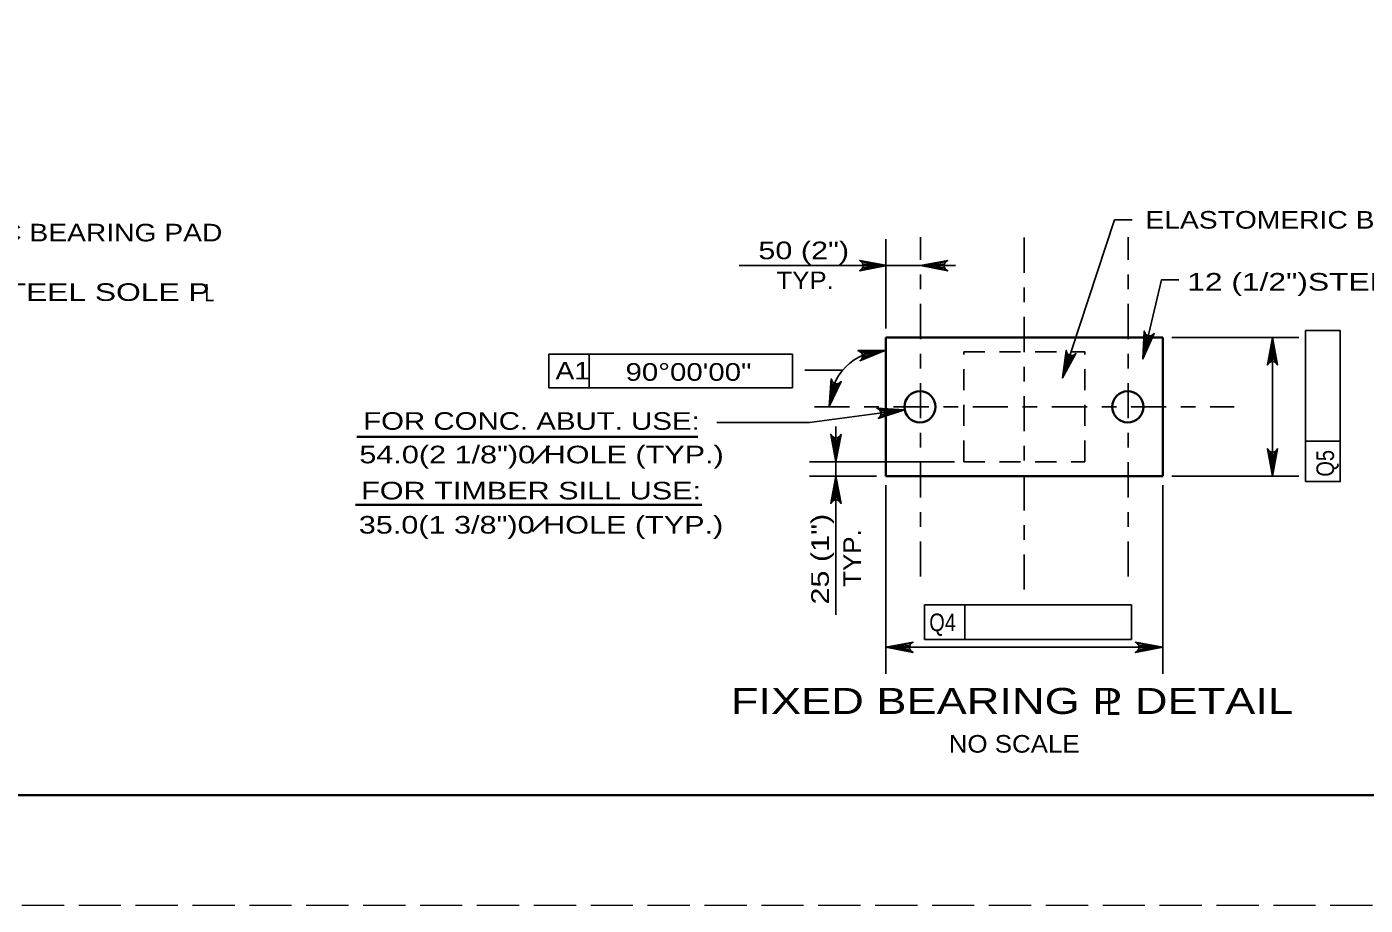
# Model space of a CAD drawing. Extents: x -11 to 79, y -154 to 0.
# Drawn here: x 14 to 23.13, y -154 to -148.01 of the extents above; entities that cross this region are included whole.
import ezdxf
from ezdxf.enums import TextEntityAlignment as Align

# ---------------------------------------------------------------- set-up
doc = ezdxf.new("R2010")
doc.units = 0
doc.header["$LTSCALE"] = 0.048
for name, pattern in [('DOT_DASHED', [7.7, 5, -1.2, 0.3, -1.2]), ('LONG_DASHED', [7.5, 6, -1.5]), ('MEDIUM_DASHED', [4.5, 3, -1.5])]:
    doc.linetypes.add(name, pattern=pattern)
for name, color, linetype, lineweight in [('1', 7, 'Continuous', 25), ('3', 7, 'Continuous', 25), ('4', 7, 'Continuous', 25), ('63', 7, 'LONG_DASHED', 13)]:
    doc.layers.add(name, color=color, linetype=linetype, lineweight=lineweight)

msp = doc.modelspace()

# ---------------------------------------------------------------- hatches: boundary and pattern name
at = {"layer": '4'}
for points in [[(19.74033, -149.61867), (19.74033, -149.65867), (19.86033, -149.63867)], [(20.21658, -149.61867), (20.21658, -149.65867), (20.09658, -149.63867)], [(21.6615, -150.16108), (21.62258, -150.152), (21.61475, -150.27342)], [(22.47825, -150.24958), (22.51825, -150.24958), (22.49825, -150.12958)], [(21.12533, -150.28867), (21.08733, -150.27617), (21.06875, -150.39633)], [(19.86742, -150.61775), (19.87267, -150.65733), (19.989, -150.62167)], [(19.5005, -150.856), (19.5405, -150.856), (19.5205, -150.976)], [(22.47825, -150.95442), (22.51825, -150.95442), (22.49825, -151.07442)], [(19.5005, -151.19442), (19.5405, -151.19442), (19.5205, -151.07442)], [(19.98033, -152.22167), (19.98033, -152.26167), (19.86033, -152.24167)], [(21.63008, -152.22167), (21.63008, -152.26167), (21.75008, -152.24167)]]:
    msp.add_hatch(color=256, dxfattribs=at).paths.add_polyline_path(points)

# ---------------------------------------------------------------- linework, layer by layer
at = {"layer": '1', "lineweight": 35}
msp.add_lwpolyline([(1.75, -153.25), (33.25, -153.25), (33.25, -132.75), (1.75, -132.75)], close=True, dxfattribs=at)
at = {"layer": '3', "lineweight": 35}
for p, q in [((19.86033, -150.12958), (21.75008, -150.12958)), ((19.86033, -151.07442), (19.86033, -150.12958)), ((21.75008, -151.07442), (21.75008, -150.12958)), ((19.86033, -151.07442), (21.75008, -151.07442))]:
    msp.add_line(p, q, dxfattribs=at)
at = {"layer": '3', "linetype": 'MEDIUM_DASHED'}
for p, q in [((21.21858, -150.976), (21.21858, -150.228)), ((20.39183, -150.976), (21.21858, -150.976))]:
    msp.add_line(p, q, dxfattribs=at)
msp.add_lwpolyline([(20.39183, -150.976), (20.39183, -150.228), (21.21858, -150.228)], dxfattribs=at)
at = {"layer": '3', "lineweight": 35}
for centre in [(20.09365, -150.60209), (21.51097, -150.60209)]:
    msp.add_circle(centre, 0.1063, dxfattribs=at)
at = {"layer": '4', "linetype": 'DOT_DASHED'}
for p, q in [((20.80525, -151.8485), (20.80525, -149.3555)), ((20.09658, -151.7595), (20.09658, -149.44442)), ((21.51392, -151.7595), (21.51392, -149.44442)), ((19.37383, -150.602), (22.23658, -150.602))]:
    msp.add_line(p, q, dxfattribs=at)
at = {"layer": '4'}
for p, q in [((19.86033, -150.06708), (19.86033, -149.45867)), ((20.09658, -149.63867), (18.86158, -149.63867)), ((20.21658, -149.63867), (20.33658, -149.63867)), ((21.81092, -150.12958), (22.67825, -150.12958)), ((22.49825, -151.07442), (22.49825, -150.12958)), ((22.72375, -151.11192), (22.72375, -150.08208)), ((22.72375, -150.08208), (22.96, -150.08208)), ((17.56275, -150.24192), (19.22375, -150.24192)), ((17.83842, -150.47258), (17.83842, -150.24192)), ((19.22375, -150.24192), (19.22375, -150.47258)), ((19.56683, -150.35225), (19.30758, -150.35225)), ((19.98917, -150.62167), (19.34083, -150.70808)), ((19.34083, -150.70808), (18.70825, -150.70808)), ((19.5205, -150.856), (19.5205, -150.736)), ((22.96, -150.83633), (22.72375, -150.83633)), ((20.32933, -150.976), (19.3405, -150.976)), ((19.5205, -150.976), (19.5205, -152.01958)), ((19.79783, -151.07442), (19.3405, -151.07442)), ((21.81258, -151.07442), (22.67825, -151.07442)), ((19.86033, -151.13692), (19.86033, -152.42167)), ((21.75008, -151.13692), (21.75008, -152.42167)), ((20.12425, -151.95225), (21.53625, -151.95225)), ((20.12425, -152.1885), (20.12425, -151.95225)), ((20.39983, -152.1885), (20.39983, -151.95225)), ((21.53625, -151.95225), (21.53625, -152.1885)), ((19.86033, -152.24167), (21.75008, -152.24167)), ((21.53625, -152.1885), (20.12425, -152.1885))]:
    msp.add_line(p, q, dxfattribs=at)
at = {"layer": '4', "lineweight": 35}
for p, q in [((16.253, -150.80617), (18.57942, -150.80617)), ((17.4485, -150.98842), (17.56808, -150.86883)), ((16.24442, -151.26992), (18.60583, -151.26992)), ((17.45217, -151.453), (17.5555, -151.34958))]:
    msp.add_line(p, q, dxfattribs=at)
at = {"layer": '4'}
for points in [[(21.06592, -150.40508), (21.42133, -149.327), (21.54133, -149.327)], [(19.86892, -149.63867), (19.6825, -149.67358), (19.69683, -149.66367), (19.70425, -149.65117), (19.70642, -149.63867), (19.70425, -149.62617), (19.69683, -149.61367), (19.6825, -149.60375), (19.86892, -149.63867), (19.69683, -149.61367), (19.70425, -149.62617), (19.86892, -149.63867), (19.70642, -149.63867), (19.70425, -149.65117), (19.86892, -149.63867), (19.69683, -149.66367)], [(20.09658, -149.63867), (20.283, -149.60375), (20.26867, -149.61367), (20.26125, -149.62617), (20.25908, -149.63867), (20.26125, -149.65117), (20.26867, -149.66367), (20.283, -149.67358), (20.09658, -149.63867), (20.26867, -149.66367), (20.26125, -149.65117), (20.09658, -149.63867), (20.25908, -149.63867), (20.26125, -149.62617), (20.09658, -149.63867), (20.26867, -149.61367)], [(21.6145, -150.27467), (21.74025, -149.73658), (21.86025, -149.73658)], [(21.6145, -150.27467), (21.62292, -150.08517), (21.62933, -150.10142), (21.63983, -150.1115), (21.6515, -150.11642), (21.66417, -150.11717), (21.678, -150.11283), (21.69092, -150.10108), (21.6145, -150.27467), (21.678, -150.11283), (21.66417, -150.11717), (21.6145, -150.27467), (21.6515, -150.11642), (21.63983, -150.1115), (21.6145, -150.27467), (21.62933, -150.10142)], [(22.49825, -150.12958), (22.53317, -150.316), (22.52325, -150.30167), (22.51075, -150.29425), (22.49825, -150.29208), (22.48575, -150.29425), (22.47325, -150.30167), (22.46333, -150.316), (22.49825, -150.12958), (22.47325, -150.30167), (22.48575, -150.29425), (22.49825, -150.12958), (22.49825, -150.29208), (22.51075, -150.29425), (22.49825, -150.12958), (22.52325, -150.30167)], [(22.96, -150.08208), (22.96, -151.11192), (22.72375, -151.11192)], [(19.22375, -150.47258), (17.56275, -150.47258), (17.56275, -150.24192)], [(19.86017, -150.21658), (19.68425, -150.2875), (19.69633, -150.27483), (19.70117, -150.26117), (19.70083, -150.2485), (19.69625, -150.23667), (19.6865, -150.22583), (19.6705, -150.21892), (19.86017, -150.21658), (19.6865, -150.22583), (19.69625, -150.23667), (19.86017, -150.21658), (19.70083, -150.2485), (19.70117, -150.26117), (19.86017, -150.21658), (19.69633, -150.27483)], [(21.06592, -150.40508), (21.09108, -150.21708), (21.09608, -150.23383), (21.10558, -150.24483), (21.11683, -150.25075), (21.12933, -150.25267), (21.1435, -150.2495), (21.1575, -150.239), (21.06592, -150.40508), (21.1435, -150.2495), (21.12933, -150.25267), (21.06592, -150.40508), (21.11683, -150.25075), (21.10558, -150.24483), (21.06592, -150.40508), (21.09608, -150.23383)], [(19.47508, -150.60058), (19.48908, -150.41142), (19.49508, -150.42783), (19.50525, -150.43825), (19.51675, -150.4435), (19.52942, -150.44467), (19.54342, -150.44067), (19.55667, -150.42933), (19.47508, -150.60058), (19.54342, -150.44067), (19.52942, -150.44467), (19.47508, -150.60058), (19.51675, -150.4435), (19.50525, -150.43825), (19.47508, -150.60058), (19.49508, -150.42783)], [(19.98917, -150.62167), (19.809, -150.68092), (19.82192, -150.66917), (19.82758, -150.65583), (19.82808, -150.64317), (19.82433, -150.631), (19.81533, -150.61958), (19.79975, -150.61167), (19.98917, -150.62167), (19.81533, -150.61958), (19.82433, -150.631), (19.98917, -150.62167), (19.82808, -150.64317), (19.82758, -150.65583), (19.98917, -150.62167), (19.82192, -150.66917)], [(19.5205, -150.976), (19.48558, -150.78958), (19.4955, -150.80392), (19.508, -150.81133), (19.5205, -150.8135), (19.533, -150.81133), (19.5455, -150.80392), (19.55542, -150.78958), (19.5205, -150.976), (19.5455, -150.80392), (19.533, -150.81133), (19.5205, -150.976), (19.5205, -150.8135), (19.508, -150.81133), (19.5205, -150.976), (19.4955, -150.80392)], [(22.49825, -151.07442), (22.46333, -150.888), (22.47325, -150.90233), (22.48575, -150.90975), (22.49825, -150.91192), (22.51075, -150.90975), (22.52325, -150.90233), (22.53317, -150.888), (22.49825, -151.07442), (22.52325, -150.90233), (22.51075, -150.90975), (22.49825, -151.07442), (22.49825, -150.91192), (22.48575, -150.90975), (22.49825, -151.07442), (22.47325, -150.90233)], [(19.5205, -151.07442), (19.55542, -151.26083), (19.5455, -151.2465), (19.533, -151.23908), (19.5205, -151.23692), (19.508, -151.23908), (19.4955, -151.2465), (19.48558, -151.26083), (19.5205, -151.07442), (19.4955, -151.2465), (19.508, -151.23908), (19.5205, -151.07442), (19.5205, -151.23692), (19.533, -151.23908), (19.5205, -151.07442), (19.5455, -151.2465)], [(19.86033, -152.24167), (20.04675, -152.20675), (20.03242, -152.21667), (20.025, -152.22917), (20.02283, -152.24167), (20.025, -152.25417), (20.03242, -152.26667), (20.04675, -152.27658), (19.86033, -152.24167), (20.03242, -152.26667), (20.025, -152.25417), (19.86033, -152.24167), (20.02283, -152.24167), (20.025, -152.22917), (19.86033, -152.24167), (20.03242, -152.21667)], [(21.75008, -152.24167), (21.56367, -152.27658), (21.578, -152.26667), (21.58542, -152.25417), (21.58758, -152.24167), (21.58542, -152.22917), (21.578, -152.21667), (21.56367, -152.20675), (21.75008, -152.24167), (21.578, -152.21667), (21.58542, -152.22917), (21.75008, -152.24167), (21.58758, -152.24167), (21.58542, -152.25417), (21.75008, -152.24167), (21.578, -152.26667)]]:
    msp.add_lwpolyline(points, dxfattribs=at)
for points in [[(19.74033, -149.61867), (19.74033, -149.65867), (19.86033, -149.63867)], [(20.21658, -149.61867), (20.21658, -149.65867), (20.09658, -149.63867)], [(21.6615, -150.16108), (21.62258, -150.152), (21.61475, -150.27342)], [(22.47825, -150.24958), (22.51825, -150.24958), (22.49825, -150.12958)], [(21.12533, -150.28867), (21.08733, -150.27617), (21.06875, -150.39633)], [(19.86742, -150.61775), (19.87267, -150.65733), (19.989, -150.62167)], [(19.5005, -150.856), (19.5405, -150.856), (19.5205, -150.976)], [(22.47825, -150.95442), (22.51825, -150.95442), (22.49825, -151.07442)], [(19.5005, -151.19442), (19.5405, -151.19442), (19.5205, -151.07442)], [(19.98033, -152.22167), (19.98033, -152.26167), (19.86033, -152.24167)], [(21.63008, -152.22167), (21.63008, -152.26167), (21.75008, -152.24167)]]:
    msp.add_lwpolyline(points, close=True, dxfattribs=at)
msp.add_arc((19.86032, -150.60199), 0.38539, 90.00223, 179.99818, dxfattribs=at)
at = {"layer": '63'}
msp.add_lwpolyline([(0, -154), (34, -154), (34, -132), (0, -132)], close=True, dxfattribs=at)

# ---------------------------------------------------------------- texts
at = {"layer": '4'}
for s, width, p in [('ELASTOMERIC BEARING PAD', 1.2, (21.63133, -149.38692)), ('ELASTOMERIC BEARING PAD', 1.2, (12.58592, -149.474)), ('12 (1/2")STEEL SOLE P', 1.35, (21.91625, -149.80942)), ('12 (1/2")STEEL SOLE P', 1.35, (12.89642, -149.87967)), ('L', 0.75, (15.21383, -149.88367)), ('90°00\'00"', 1.25, (18.0855, -150.42425)), ('FOR CONC. ABUT. USE:', 1.25, (16.29583, -150.75858)), ('54.0(2 1/8")0 HOLE (TYP.)', 1.3, (16.27, -150.987)), ('FOR TIMBER SILL USE:', 1.3, (16.282, -151.23317)), ('35.0(1 3/8")0 HOLE (TYP.)', 1.3, (16.2665, -151.46625)), ('NO SCALE', 1.1, (20.29, -152.95967))]:
    msp.add_text(s, height=0.12, dxfattribs=dict(at, width=width)).set_placement(p)
for s, height, width, p in [('50 (2")', 0.12, 1.3, (19.30079, -149.5955)), ('TYP.', 0.12, 1.1, (19.31021, -149.79958)), ('A1', 0.12, 1.2, (17.72571, -150.41533)), ('Q4', 0.12, 0.85, (20.24788, -152.13125)), ('FIXED BEARING P DETAIL', 0.1772, 1.3, (20.72096, -152.696)), ('L', 0.1772, 0.75, (21.41033, -152.70225))]:
    msp.add_text(s, height=height, dxfattribs=dict(at, width=width)).set_placement(p, align=Align.CENTER)
for s, width, p in [('Q5', 0.85, (22.91758, -150.98704)), ('25 (1")', 1.3, (19.47225, -151.64079)), ('TYP.', 1.1, (19.69075, -151.63279))]:
    msp.add_text(s, height=0.12, rotation=90, dxfattribs=dict(at, width=width)).set_placement(p, align=Align.CENTER)

doc.saveas('drawing.dxf')
